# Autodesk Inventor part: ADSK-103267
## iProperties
Created: 2000-08
Part Number: ADSK-103267
Description: Hex Cap Screw
Document SubType Name: Modeling
Standard: ANSI B18.2.1 - 1/2 - 13 - 1 3/4
Designer: gao
Density: 1 g/cm^3
Control State: 0
Master: False
Checked Out: False
Shininess: 0.0
Density: 0.0
Volumn: 0.0
Area: 0.0
PropertySet Name: Model Information
Author: gao
